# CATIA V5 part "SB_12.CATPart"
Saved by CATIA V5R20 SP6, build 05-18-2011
Part number: SB_12
Material "Green Blue": density 7860 kg/m3, Young's modulus 2e+11 Pa, Poisson ratio 0.266
Bounding box of the stored display mesh (mm): x 0 to 79, y 0 to 948, z 0 to 49.2
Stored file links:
  E:\#01 CATIA Lecture Materials\#06 DMU\#11 DMU Page01 KIN EX11\SB_12.CATPart
  C:\Program Files\Dassault Systemes\B20\win_b64\startup\materials\Catalog.CATMaterial
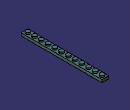
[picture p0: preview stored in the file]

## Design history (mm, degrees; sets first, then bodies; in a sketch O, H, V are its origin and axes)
Body1 (main body), material "Green Blue"
  Sketch1 on xy-plane, origin (0, 0, 0), H (1, 0, 0), V (0, 1, 0)
    circle A1 centre (39.5, 39.5) radius 24.5
    point P1 (39.5, 39.5)
    radius A1 = 24.5
    distance P1 H = 39.5
    distance P1 V = 39.5
  Pad1: profile Sketch1, direction (0, 0, 1), length 49.2
  RectPattern1: of Pad1, direction 1 instances 12, spacing 79, along yz-plane
  Sketch2 on xy-plane, origin (0, 0, 0), H (1, 0, 0), V (0, 1, 0)
    point P1 (0, 948)
    line L1 (0, 948) -> (79, 948)
    line L2 (79, 948) -> (79, 0)
    line L3 (79, 0) -> (0, 0)
    line L4 (0, 0) -> (0, 948)
    point P3 (79, 0)
    distance L2 L4 = 79
    distance L1 L3 = 948 {= RectPattern1.Nb1 * 79mm}
    coincidence: P1 V, P3 H
    horizontal: L1 H, L3 H
    vertical: L2 V, L4 V
  Pad2: profile Sketch2, direction (0, 0, 1), length 32
  Shell1: ExtOffset 0, Face face of Pad2, IntOffset 15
